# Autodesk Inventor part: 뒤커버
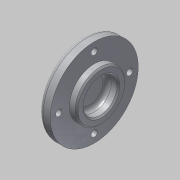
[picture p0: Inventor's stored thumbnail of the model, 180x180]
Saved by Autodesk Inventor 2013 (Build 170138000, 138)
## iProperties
Created: 2015-12
Part Number: 뒤커버
Document SubType Name: Modeling
Designer: mdu
Density: 2.71 g/cm^3
Material: 알루미늄 6061
Mass: 72.2029 g
Surface Area: 89.061 cm^2
Volume: 26.6431 cm^3
Author: mdu
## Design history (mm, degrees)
sketch "스케치1"
  geometry: L1 (-8, 0)-(8, 0); L2 (-8, 0)-(-8, 15.5); L3 (-8, 15.5)-(-5, 18.5); L4 (-5, 18.5)-(-5, 31); L5 (-5, 31)-(3, 31); L6 (3, 31)-(3, 17.5); L7 (3, 17.5)-(8, 17.5); L8 (8, 17.5)-(8, 0); 2 further points
  constraints: 16 end point, 4 parallel, 2 perpendicular, 1 coincident, 1 horizontal, 1 midpoint
  dimensions: "d0" = 16 distance of L1.start L1.end; "d1" = 62 diameter of L5 L1; "d2" = 35 diameter of L7 L1; "d3" = 37 diameter of L3.end L1; "d5" = 8 distance of L4.end L5.end; "d34" = 135 deg angle of L4 L3; "d36" = 5 distance of L6.end L7.end
revolve "회전1" sketch "스케치1" stored, may be unused: angle "d6" = 90 deg
sketch "스케치2" dims "d32" = 50
  geometry: 3 further points
  constraints: 2 vertical alignment, 1 coincident, 2 other
hole "구멍1" sketch "스케치2" at (0, 25) diameter "d8" = 4.5; stored, may be unused: countersink angle "d12" = 90 deg, drill point angle "d14" = 118 deg; dims "d9" = 6, "d10" = 8, "d11" = 4.4, "d13" = 8
hole "구멍2" diameter "d20" = 24; stored, may be unused: countersink angle "d24" = 90 deg, drill point angle "d26" = 0 deg; dims "d18" = 10, "d19" = 10, "d21" = 6, "d22" = 8, "d23" = 4.4, "d25" = 8
fillet "모깎기1" dims "d27" = 3
fillet "모깎기2" dims "d28" = 3
chamfer "모따기1" distance "d29" = 1; stored, may be unused: second distance "d30" = 2, angle "d31" = 45 deg
node "솔리드1"
pattern_circular "원형 패턴1" dims angle "d16" = 360 deg
